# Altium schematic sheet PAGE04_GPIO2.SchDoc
size 381 x 304 mm; SheetNumber: 5; SheetTotal: 28
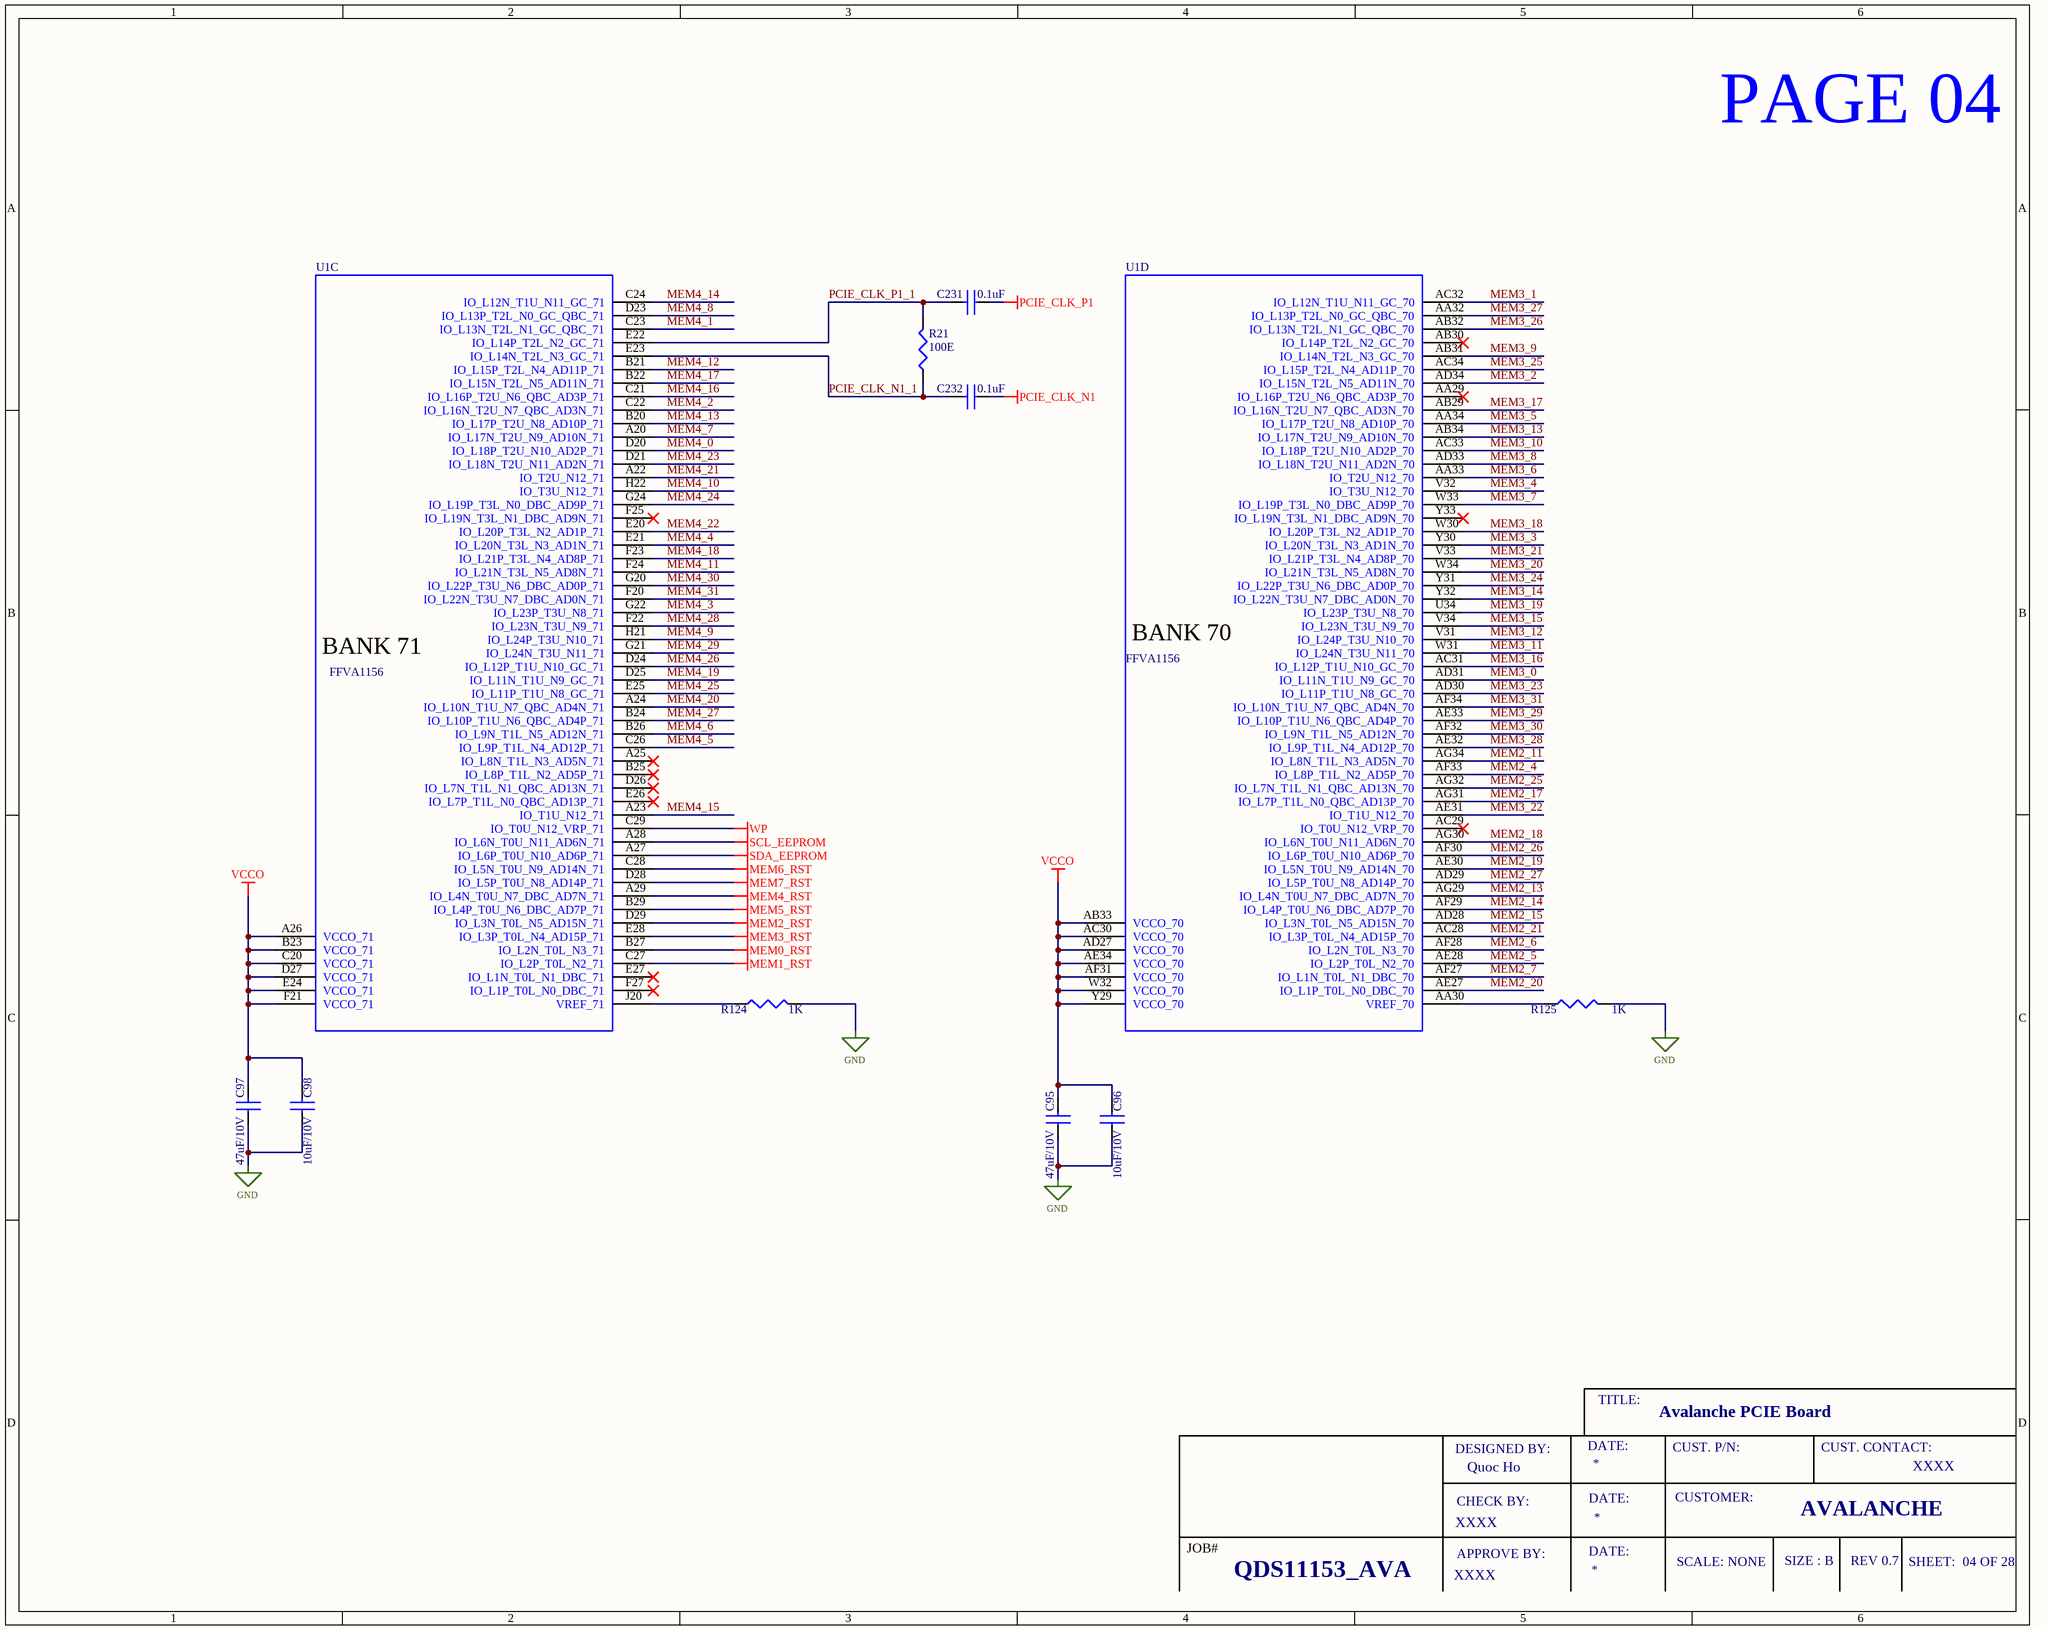
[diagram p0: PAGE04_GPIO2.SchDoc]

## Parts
C95  47uF/10V  [CN_0805]
C96  10uF/10V  [CN_0402]
C97  47uF/10V  [CN_0805]
C98  10uF/10V  [CN_0402]
C231  0.1uF  [CN_0402]
C232  0.1uF  [CN_0402]
R21  100E  [RN_0402]
R124  1K  [RN_0402]
R125  1K  [RN_0402]
U1  FFVA1156  [FFVA1156]  (parts C,D of 25)

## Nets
GND: C95.1 C96.1 C97.1 C98.1 R124.2 R125.2
MEM0_RST: U1.B27(IO_L2N_T0L_N3_71)
MEM1_RST: U1.C27(IO_L2P_T0L_N2_71)
MEM2_RST: U1.D29(IO_L3N_T0L_N5_AD15N_71)
MEM3_RST: U1.E28(IO_L3P_T0L_N4_AD15P_71)
MEM4_RST: U1.A29(IO_L4N_T0U_N7_DBC_AD7N_71)
MEM5_RST: U1.B29(IO_L4P_T0U_N6_DBC_AD7P_71)
MEM6_RST: U1.C28(IO_L5N_T0U_N9_AD14N_71)
MEM7_RST: U1.D28(IO_L5P_T0U_N8_AD14P_71)
PCIE_CLK_N1: C232.1
PCIE_CLK_P1: C231.1
SCL_EEPROM: U1.A28(IO_L6N_T0U_N11_AD6N_71)
SDA_EEPROM: U1.A27(IO_L6P_T0U_N10_AD6P_71)
VCCO: C95.2 C96.2 C97.2 C98.2 U1.A26(VCCO_71) U1.AB33(VCCO_70) U1.AC30(VCCO_70) U1.AD27(VCCO_70) U1.AE34(VCCO_70) U1.AF31(VCCO_70) U1.B23(VCCO_71) U1.C20(VCCO_71) U1.D27(VCCO_71) U1.E24(VCCO_71) U1.F21(VCCO_71) U1.W32(VCCO_70) U1.Y29(VCCO_70)
WP: U1.C29(IO_T0U_N12_VRP_71)
MEM2_4: U1.AF33(IO_L8P_T1L_N2_AD5P_70)
MEM2_5: U1.AE28(IO_L2P_T0L_N2_70)
MEM2_6: U1.AF28(IO_L2N_T0L_N3_70)
MEM2_7: U1.AF27(IO_L1N_T0L_N1_DBC_70)
MEM2_11: U1.AG34(IO_L8N_T1L_N3_AD5N_70)
MEM2_13: U1.AG29(IO_L4N_T0U_N7_DBC_AD7N_70)
MEM2_14: U1.AF29(IO_L4P_T0U_N6_DBC_AD7P_70)
MEM2_15: U1.AD28(IO_L3N_T0L_N5_AD15N_70)
MEM2_17: U1.AG31(IO_L7P_T1L_N0_QBC_AD13P_70)
MEM2_18: U1.AG30(IO_L6N_T0U_N11_AD6N_70)
MEM2_19: U1.AE30(IO_L5N_T0U_N9_AD14N_70)
MEM2_20: U1.AE27(IO_L1P_T0L_N0_DBC_70)
MEM2_21: U1.AC28(IO_L3P_T0L_N4_AD15P_70)
MEM2_25: U1.AG32(IO_L7N_T1L_N1_QBC_AD13N_70)
MEM2_26: U1.AF30(IO_L6P_T0U_N10_AD6P_70)
MEM2_27: U1.AD29(IO_L5P_T0U_N8_AD14P_70)
MEM3_0: U1.AD31(IO_L11N_T1U_N9_GC_70)
MEM3_1: U1.AC32(IO_L12N_T1U_N11_GC_70)
MEM3_2: U1.AD34(IO_L15N_T2L_N5_AD11N_70)
MEM3_3: U1.Y30(IO_L20N_T3L_N3_AD1N_70)
MEM3_4: U1.V32(IO_T3U_N12_70)
MEM3_5: U1.AA34(IO_L17P_T2U_N8_AD10P_70)
MEM3_6: U1.AA33(IO_T2U_N12_70)
MEM3_7: U1.W33(IO_L19P_T3L_N0_DBC_AD9P_70)
MEM3_8: U1.AD33(IO_L18N_T2U_N11_AD2N_70)
MEM3_9: U1.AB31(IO_L14N_T2L_N3_GC_70)
MEM3_10: U1.AC33(IO_L18P_T2U_N10_AD2P_70)
MEM3_11: U1.W31(IO_L24N_T3U_N11_70)
MEM3_12: U1.V31(IO_L24P_T3U_N10_70)
MEM3_13: U1.AB34(IO_L17N_T2U_N9_AD10N_70)
MEM3_14: U1.Y32(IO_L22N_T3U_N7_DBC_AD0N_70)
MEM3_15: U1.V34(IO_L23N_T3U_N9_70)
MEM3_16: U1.AC31(IO_L12P_T1U_N10_GC_70)
MEM3_17: U1.AB29(IO_L16N_T2U_N7_QBC_AD3N_70)
MEM3_18: U1.W30(IO_L20P_T3L_N2_AD1P_70)
MEM3_19: U1.U34(IO_L23P_T3U_N8_70)
MEM3_20: U1.W34(IO_L21N_T3L_N5_AD8N_70)
MEM3_21: U1.V33(IO_L21P_T3L_N4_AD8P_70)
MEM3_22: U1.AE31(IO_T1U_N12_70)
MEM3_23: U1.AD30(IO_L11P_T1U_N8_GC_70)
MEM3_24: U1.Y31(IO_L22P_T3U_N6_DBC_AD0P_70)
MEM3_25: U1.AC34(IO_L15P_T2L_N4_AD11P_70)
MEM3_26: U1.AB32(IO_L13N_T2L_N1_GC_QBC_70)
MEM3_27: U1.AA32(IO_L13P_T2L_N0_GC_QBC_70)
MEM3_28: U1.AE32(IO_L9P_T1L_N4_AD12P_70)
MEM3_29: U1.AE33(IO_L10P_T1U_N6_QBC_AD4P_70)
MEM3_30: U1.AF32(IO_L9N_T1L_N5_AD12N_70)
MEM3_31: U1.AF34(IO_L10N_T1U_N7_QBC_AD4N_70)
MEM4_0: U1.D20(IO_L18P_T2U_N10_AD2P_71)
MEM4_1: U1.C23(IO_L13N_T2L_N1_GC_QBC_71)
MEM4_2: U1.C22(IO_L16N_T2U_N7_QBC_AD3N_71)
MEM4_3: U1.G22(IO_L23P_T3U_N8_71)
MEM4_4: U1.E21(IO_L20N_T3L_N3_AD1N_71)
MEM4_5: U1.C26(IO_L9P_T1L_N4_AD12P_71)
MEM4_6: U1.B26(IO_L9N_T1L_N5_AD12N_71)
MEM4_7: U1.A20(IO_L17N_T2U_N9_AD10N_71)
MEM4_8: U1.D23(IO_L13P_T2L_N0_GC_QBC_71)
MEM4_9: U1.H21(IO_L24P_T3U_N10_71)
MEM4_10: U1.H22(IO_T3U_N12_71)
MEM4_11: U1.F24(IO_L21N_T3L_N5_AD8N_71)
MEM4_12: U1.B21(IO_L15P_T2L_N4_AD11P_71)
MEM4_13: U1.B20(IO_L17P_T2U_N8_AD10P_71)
MEM4_14: U1.C24(IO_L12N_T1U_N11_GC_71)
MEM4_15: U1.A23(IO_T1U_N12_71)
MEM4_16: U1.C21(IO_L16P_T2U_N6_QBC_AD3P_71)
MEM4_17: U1.B22(IO_L15N_T2L_N5_AD11N_71)
MEM4_18: U1.F23(IO_L21P_T3L_N4_AD8P_71)
MEM4_19: U1.D25(IO_L11N_T1U_N9_GC_71)
MEM4_20: U1.A24(IO_L10N_T1U_N7_QBC_AD4N_71)
MEM4_21: U1.A22(IO_T2U_N12_71)
MEM4_22: U1.E20(IO_L20P_T3L_N2_AD1P_71)
MEM4_23: U1.D21(IO_L18N_T2U_N11_AD2N_71)
MEM4_24: U1.G24(IO_L19P_T3L_N0_DBC_AD9P_71)
MEM4_25: U1.E25(IO_L11P_T1U_N8_GC_71)
MEM4_26: U1.D24(IO_L12P_T1U_N10_GC_71)
MEM4_27: U1.B24(IO_L10P_T1U_N6_QBC_AD4P_71)
MEM4_28: U1.F22(IO_L23N_T3U_N9_71)
MEM4_29: U1.G21(IO_L24N_T3U_N11_71)
MEM4_30: U1.G20(IO_L22P_T3U_N6_DBC_AD0P_71)
MEM4_31: U1.F20(IO_L22N_T3U_N7_DBC_AD0N_71)
PCIE_CLK_N1_1: C232.2 R21.1 U1.E23(IO_L14N_T2L_N3_GC_71)
PCIE_CLK_P1_1: C231.2 R21.2 U1.E22(IO_L14P_T2L_N2_GC_71)
NetR124_1: R124.1 U1.J20(VREF_71)
NetR125_1: R125.1 U1.AA30(VREF_70)

Not connected (* = marked no-connect by the designer): U1 A25(IO_L8N_T1L_N3_AD5N_71)* AA29(IO_L16P_T2U_N6_QBC_AD3P_70)* AB30(IO_L14P_T2L_N2_GC_70)* AC29(IO_T0U_N12_VRP_70)* B25(IO_L8P_T1L_N2_AD5P_71)* D26(IO_L7N_T1L_N1_QBC_AD13N_71)* E26(IO_L7P_T1L_N0_QBC_AD13P_71)* E27(IO_L1N_T0L_N1_DBC_71)* F25(IO_L19N_T3L_N1_DBC_AD9N_71)* F27(IO_L1P_T0L_N0_DBC_71)* Y33(IO_L19N_T3L_N1_DBC_AD9N_70)*

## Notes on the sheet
- PAGE 04
- (near U1) BANK 71
- (near U1) BANK 70
- DATE:
- TITLE:
- Avalanche PCIE Board
- DESIGNED BY:
- CHECK BY:
- Quoc Ho
- CUST. P/N:
- CUSTOMER:
- AVALANCHE
- CUST. CONTACT:
- XXXX
- JOB#
- QDS11153_AVA
- APPROVE BY:
- SCALE: NONE
- SIZE : B
- REV 0.7
- SHEET:  04 OF 28

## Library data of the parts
C95 = CAP: CAP CER 47UF 10V X5R 0805; Manufacturer: Murata Electronics; Manufacturer Part Number: GRM21BR61A476ME15K
C96 C98 = CAP: CAP CER 10UF 10V X5R 0402; Manufacturer Part Number: GRM155R61A106ME11D; Manufacturer: Murata Electronics
C97 = CAP: CAP CER 47UF 10V X5R 0805; Manufacturer Part Number: GRM21BR61A476ME15K; Manufacturer: Murata Electronics
C231 C232 = CAP: CAP CER 0.1UF 50V X7R 0402; Manufacturer: Murata Electronics; Manufacturer Part Number: GCM155R71H104KE02J
R21 = RES: RES 100 OHM 1% 1/16W 0402; Manufacturer Part Number: RC0402FR-07100RL; Manufacturer: YAGEO
R124 R125 = RES: RES 1K OHM 1% 1/16W 0402; Manufacturer Part Number: RC0402FR-131KL; Manufacturer: YAGEO
U1 = FFVA1156: IC FPGA 516 I/O 1156FCBGA; Manufacturer Part Number: XCKU15P-1FFVA1156E; Manufacturer: AMD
